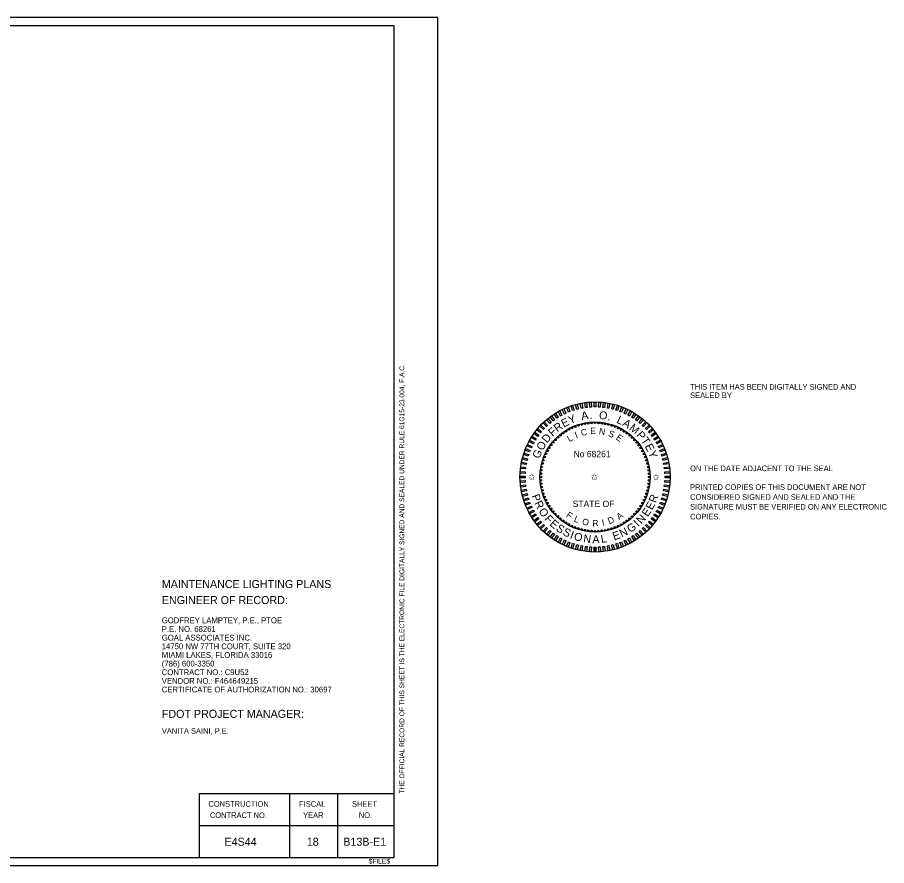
# Model space of a CAD drawing. Extents: x -820.2 to -798.1, y -2199.1 to -2188.5.
# Drawn here: x -808.98 to -798.12, y -2199.12 to -2188.52 of the extents above; entities that cross this region are included whole.
import ezdxf

# ---------------------------------------------------------------- set-up
doc = ezdxf.new("R2010")
doc.units = 0
for name, color, linetype in [('ActivePointCell_dp', 7, 'Continuous'), ('AdhocPoint_dp', 7, 'Continuous'), ('Logo_dp', 7, 'Continuous'), ('NonPlottingEle_dp', 7, 'Continuous'), ('PlotBorder_dp', 7, 'Continuous'), ('SheetBorder_dp', 7, 'Continuous'), ('SheetLines_dp', 7, 'Continuous'), ('TextLabel', 7, 'Continuous'), ('TextMinor', 7, 'Continuous'), ('TextMisc', 7, 'Continuous'), ('TextNotes', 7, 'Continuous')]:
    doc.layers.add(name, color=color, linetype=linetype)

msp = doc.modelspace()

# ---------------------------------------------------------------- linework, layer by layer
at = {"layer": 'ActivePointCell_dp'}
msp.add_line((-804.277, -2188.624), (-804.277, -2188.624), dxfattribs=at)
at = {"layer": 'AdhocPoint_dp'}
msp.add_line((-803.727, -2199.124), (-803.727, -2199.124), dxfattribs=at)
at = {"layer": 'Logo_dp'}
for p, q in [((-801.773, -2195.205), (-801.774, -2195.142)), ((-801.763, -2195.205), (-801.764, -2195.142)), ((-801.753, -2195.204), (-801.754, -2195.142))]:
    msp.add_line(p, q, dxfattribs=at)
for points in [[(-801.917, -2193.406), (-801.937, -2193.409), (-801.949, -2193.348), (-801.929, -2193.344)], [(-801.863, -2193.398), (-801.883, -2193.4), (-801.891, -2193.338), (-801.871, -2193.336)], [(-801.808, -2193.393), (-801.828, -2193.394), (-801.832, -2193.332), (-801.812, -2193.331)], [(-801.753, -2193.392), (-801.773, -2193.392), (-801.773, -2193.33), (-801.753, -2193.33)], [(-801.698, -2193.394), (-801.718, -2193.393), (-801.714, -2193.331), (-801.694, -2193.332)], [(-801.644, -2193.4), (-801.664, -2193.398), (-801.656, -2193.336), (-801.636, -2193.338)], [(-801.589, -2193.409), (-801.609, -2193.406), (-801.598, -2193.344), (-801.578, -2193.348)], [(-802.176, -2193.495), (-802.194, -2193.505), (-802.224, -2193.45), (-802.206, -2193.441)], [(-802.127, -2193.471), (-802.145, -2193.48), (-802.172, -2193.423), (-802.153, -2193.414)], [(-802.076, -2193.45), (-802.095, -2193.457), (-802.118, -2193.399), (-802.099, -2193.392)], [(-802.024, -2193.432), (-802.043, -2193.438), (-802.063, -2193.379), (-802.043, -2193.372)], [(-801.971, -2193.417), (-801.991, -2193.422), (-802.006, -2193.361), (-801.987, -2193.356)], [(-801.536, -2193.422), (-801.555, -2193.417), (-801.54, -2193.357), (-801.52, -2193.362)], [(-801.483, -2193.438), (-801.502, -2193.432), (-801.483, -2193.372), (-801.464, -2193.379)], [(-801.432, -2193.457), (-801.451, -2193.45), (-801.428, -2193.392), (-801.409, -2193.399)], [(-801.382, -2193.48), (-801.4, -2193.471), (-801.373, -2193.415), (-801.355, -2193.423)], [(-801.333, -2193.505), (-801.351, -2193.495), (-801.321, -2193.441), (-801.303, -2193.45)], [(-802.313, -2193.586), (-802.329, -2193.599), (-802.369, -2193.551), (-802.353, -2193.538)], [(-802.269, -2193.553), (-802.286, -2193.565), (-802.323, -2193.514), (-802.306, -2193.503)], [(-802.224, -2193.523), (-802.241, -2193.534), (-802.274, -2193.481), (-802.257, -2193.47)], [(-801.286, -2193.534), (-801.303, -2193.523), (-801.27, -2193.47), (-801.252, -2193.481)], [(-801.241, -2193.565), (-801.257, -2193.553), (-801.22, -2193.503), (-801.204, -2193.515)], [(-801.198, -2193.599), (-801.213, -2193.586), (-801.174, -2193.538), (-801.158, -2193.551)], [(-802.431, -2193.701), (-802.444, -2193.717), (-802.492, -2193.677), (-802.479, -2193.662)], [(-802.394, -2193.661), (-802.408, -2193.675), (-802.454, -2193.633), (-802.44, -2193.618)], [(-802.355, -2193.622), (-802.37, -2193.636), (-802.412, -2193.59), (-802.398, -2193.577)], [(-801.157, -2193.636), (-801.172, -2193.622), (-801.129, -2193.577), (-801.114, -2193.591)], [(-801.119, -2193.675), (-801.132, -2193.661), (-801.087, -2193.618), (-801.073, -2193.633)], [(-801.083, -2193.717), (-801.096, -2193.702), (-801.047, -2193.662), (-801.035, -2193.677)], [(-802.497, -2193.79), (-802.508, -2193.807), (-802.56, -2193.773), (-802.549, -2193.756)], [(-802.465, -2193.744), (-802.477, -2193.761), (-802.528, -2193.724), (-802.516, -2193.708)], [(-801.049, -2193.761), (-801.061, -2193.745), (-801.011, -2193.708), (-800.999, -2193.724)], [(-801.019, -2193.807), (-801.03, -2193.79), (-800.977, -2193.756), (-800.966, -2193.773)], [(-802.551, -2193.885), (-802.559, -2193.903), (-802.616, -2193.877), (-802.607, -2193.859)], [(-802.525, -2193.837), (-802.535, -2193.854), (-802.59, -2193.824), (-802.58, -2193.806)], [(-800.992, -2193.854), (-801.001, -2193.837), (-800.947, -2193.807), (-800.937, -2193.824)], [(-800.967, -2193.904), (-800.976, -2193.885), (-800.919, -2193.859), (-800.911, -2193.877)], [(-802.592, -2193.987), (-802.599, -2194.006), (-802.658, -2193.987), (-802.652, -2193.968)], [(-802.573, -2193.935), (-802.581, -2193.954), (-802.639, -2193.931), (-802.631, -2193.912)], [(-800.946, -2193.954), (-800.953, -2193.936), (-800.895, -2193.913), (-800.888, -2193.931)], [(-800.928, -2194.006), (-800.934, -2193.987), (-800.875, -2193.968), (-800.869, -2193.987)], [(-802.621, -2194.093), (-802.625, -2194.113), (-802.686, -2194.101), (-802.682, -2194.081)], [(-802.608, -2194.04), (-802.613, -2194.059), (-802.674, -2194.044), (-802.669, -2194.024)], [(-800.913, -2194.059), (-800.918, -2194.04), (-800.858, -2194.024), (-800.853, -2194.044)], [(-800.902, -2194.113), (-800.906, -2194.093), (-800.844, -2194.082), (-800.841, -2194.101)], [(-802.636, -2194.202), (-802.637, -2194.222), (-802.7, -2194.218), (-802.698, -2194.198)], [(-802.63, -2194.147), (-802.633, -2194.167), (-802.695, -2194.159), (-802.692, -2194.139)], [(-800.894, -2194.167), (-800.897, -2194.147), (-800.835, -2194.14), (-800.832, -2194.16)], [(-800.889, -2194.222), (-800.891, -2194.202), (-800.828, -2194.198), (-800.827, -2194.218)], [(-802.638, -2194.257), (-802.638, -2194.277), (-802.701, -2194.277), (-802.701, -2194.257)], [(-802.637, -2194.312), (-802.636, -2194.332), (-802.698, -2194.336), (-802.7, -2194.316)], [(-800.891, -2194.332), (-800.889, -2194.312), (-800.827, -2194.316), (-800.828, -2194.336)], [(-800.888, -2194.277), (-800.888, -2194.257), (-800.826, -2194.257), (-800.826, -2194.277)], [(-802.633, -2194.367), (-802.63, -2194.387), (-802.692, -2194.394), (-802.695, -2194.374)], [(-802.625, -2194.421), (-802.621, -2194.441), (-802.682, -2194.453), (-802.686, -2194.433)], [(-800.906, -2194.441), (-800.902, -2194.421), (-800.841, -2194.433), (-800.844, -2194.453)], [(-800.897, -2194.387), (-800.894, -2194.367), (-800.832, -2194.375), (-800.835, -2194.395)], [(-802.613, -2194.475), (-802.608, -2194.494), (-802.669, -2194.51), (-802.674, -2194.49)], [(-802.599, -2194.528), (-802.592, -2194.547), (-802.652, -2194.566), (-802.658, -2194.547)], [(-800.934, -2194.547), (-800.928, -2194.528), (-800.869, -2194.547), (-800.875, -2194.566)], [(-800.918, -2194.494), (-800.913, -2194.475), (-800.853, -2194.49), (-800.858, -2194.51)], [(-802.581, -2194.58), (-802.573, -2194.598), (-802.631, -2194.621), (-802.639, -2194.603)], [(-802.559, -2194.63), (-802.551, -2194.649), (-802.607, -2194.675), (-802.616, -2194.657)], [(-800.976, -2194.649), (-800.967, -2194.631), (-800.911, -2194.657), (-800.919, -2194.675)], [(-800.954, -2194.599), (-800.946, -2194.58), (-800.888, -2194.603), (-800.895, -2194.622)], [(-802.535, -2194.68), (-802.525, -2194.697), (-802.58, -2194.727), (-802.59, -2194.71)], [(-802.508, -2194.727), (-802.497, -2194.744), (-802.55, -2194.778), (-802.56, -2194.761)], [(-801.03, -2194.744), (-801.019, -2194.727), (-800.966, -2194.761), (-800.977, -2194.778)], [(-801.001, -2194.697), (-800.992, -2194.68), (-800.937, -2194.71), (-800.947, -2194.728)], [(-802.477, -2194.773), (-802.465, -2194.789), (-802.516, -2194.826), (-802.528, -2194.81)], [(-802.444, -2194.817), (-802.431, -2194.832), (-802.479, -2194.872), (-802.492, -2194.857)], [(-802.408, -2194.859), (-802.394, -2194.873), (-802.44, -2194.916), (-802.454, -2194.901)], [(-801.132, -2194.873), (-801.119, -2194.859), (-801.073, -2194.901), (-801.087, -2194.916)], [(-801.096, -2194.833), (-801.083, -2194.817), (-801.035, -2194.857), (-801.048, -2194.872)], [(-801.061, -2194.79), (-801.05, -2194.773), (-800.999, -2194.81), (-801.011, -2194.826)], [(-802.37, -2194.898), (-802.355, -2194.912), (-802.398, -2194.957), (-802.413, -2194.943)], [(-802.329, -2194.935), (-802.313, -2194.948), (-802.353, -2194.996), (-802.369, -2194.983)], [(-802.286, -2194.969), (-802.27, -2194.981), (-802.306, -2195.031), (-802.323, -2195.019)], [(-801.257, -2194.981), (-801.241, -2194.969), (-801.204, -2195.02), (-801.221, -2195.031)], [(-801.213, -2194.948), (-801.198, -2194.935), (-801.158, -2194.983), (-801.174, -2194.996)], [(-801.172, -2194.912), (-801.157, -2194.898), (-801.114, -2194.944), (-801.129, -2194.957)], [(-802.241, -2195), (-802.224, -2195.011), (-802.257, -2195.064), (-802.274, -2195.053)], [(-802.194, -2195.029), (-802.176, -2195.039), (-802.206, -2195.093), (-802.224, -2195.084)], [(-802.145, -2195.054), (-802.127, -2195.063), (-802.153, -2195.12), (-802.172, -2195.111)], [(-802.095, -2195.077), (-802.076, -2195.084), (-802.099, -2195.142), (-802.118, -2195.135)], [(-801.451, -2195.084), (-801.432, -2195.077), (-801.409, -2195.135), (-801.428, -2195.142)], [(-801.4, -2195.063), (-801.382, -2195.055), (-801.355, -2195.111), (-801.373, -2195.12)], [(-801.351, -2195.039), (-801.333, -2195.029), (-801.303, -2195.084), (-801.321, -2195.093)], [(-801.303, -2195.011), (-801.286, -2195), (-801.253, -2195.053), (-801.27, -2195.064)], [(-802.043, -2195.096), (-802.024, -2195.102), (-802.044, -2195.162), (-802.063, -2195.155)], [(-801.991, -2195.112), (-801.971, -2195.117), (-801.987, -2195.178), (-802.006, -2195.172)], [(-801.937, -2195.125), (-801.918, -2195.128), (-801.929, -2195.19), (-801.949, -2195.186)], [(-801.883, -2195.134), (-801.863, -2195.136), (-801.871, -2195.198), (-801.891, -2195.196)], [(-801.828, -2195.14), (-801.808, -2195.141), (-801.812, -2195.203), (-801.832, -2195.202)], [(-801.774, -2195.142), (-801.753, -2195.142), (-801.753, -2195.204), (-801.774, -2195.204)], [(-801.719, -2195.141), (-801.698, -2195.14), (-801.695, -2195.202), (-801.715, -2195.203)], [(-801.664, -2195.136), (-801.644, -2195.134), (-801.636, -2195.196), (-801.656, -2195.198)], [(-801.609, -2195.128), (-801.59, -2195.125), (-801.578, -2195.186), (-801.598, -2195.19)], [(-801.556, -2195.117), (-801.536, -2195.112), (-801.521, -2195.173), (-801.54, -2195.178)], [(-801.503, -2195.102), (-801.483, -2195.096), (-801.464, -2195.156), (-801.483, -2195.162)]]:
    msp.add_lwpolyline(points, close=True, dxfattribs=at)
for centre in [(-802.089, -2193.673), (-802.051, -2193.654), (-802.012, -2193.637), (-801.972, -2193.623), (-801.931, -2193.611), (-801.89, -2193.601), (-801.848, -2193.595), (-801.805, -2193.591), (-801.763, -2193.59), (-801.72, -2193.591), (-801.678, -2193.595), (-801.636, -2193.602), (-801.594, -2193.611), (-801.553, -2193.623), (-801.513, -2193.637), (-801.474, -2193.654), (-801.437, -2193.674), (-802.227, -2193.773), (-802.195, -2193.745), (-802.161, -2193.719), (-802.126, -2193.695), (-801.4, -2193.695), (-801.365, -2193.719), (-801.331, -2193.745), (-801.299, -2193.774), (-802.311, -2193.868), (-802.285, -2193.835), (-802.257, -2193.803), (-801.269, -2193.804), (-801.241, -2193.836), (-801.215, -2193.869), (-802.376, -2193.978), (-802.357, -2193.94), (-802.335, -2193.904), (-801.191, -2193.904), (-801.169, -2193.941), (-801.15, -2193.979), (-802.419, -2194.098), (-802.408, -2194.057), (-802.393, -2194.017), (-801.133, -2194.018), (-801.119, -2194.058), (-801.107, -2194.099), (-802.439, -2194.224), (-802.435, -2194.182), (-802.429, -2194.14), (-801.098, -2194.141), (-801.091, -2194.183), (-801.087, -2194.225), (-802.441, -2194.266), (-802.44, -2194.309), (-801.087, -2194.31), (-801.086, -2194.268), (-802.436, -2194.351), (-802.429, -2194.393), (-802.42, -2194.435), (-801.107, -2194.436), (-801.098, -2194.395), (-801.091, -2194.352), (-802.408, -2194.476), (-802.393, -2194.516), (-801.134, -2194.517), (-801.119, -2194.477), (-802.377, -2194.555), (-802.357, -2194.593), (-802.336, -2194.63), (-801.192, -2194.63), (-801.17, -2194.594), (-801.151, -2194.556), (-802.312, -2194.665), (-802.286, -2194.698), (-802.258, -2194.73), (-802.228, -2194.76), (-801.3, -2194.761), (-801.27, -2194.731), (-801.242, -2194.699), (-801.216, -2194.666), (-802.196, -2194.789), (-802.162, -2194.815), (-802.127, -2194.839), (-802.09, -2194.86), (-802.052, -2194.88), (-801.475, -2194.88), (-801.438, -2194.861), (-801.401, -2194.839), (-801.366, -2194.815), (-801.332, -2194.789), (-802.013, -2194.897), (-801.973, -2194.911), (-801.932, -2194.923), (-801.891, -2194.932), (-801.849, -2194.939), (-801.806, -2194.943), (-801.763, -2194.945), (-801.721, -2194.943), (-801.679, -2194.939), (-801.637, -2194.933), (-801.595, -2194.923), (-801.555, -2194.911), (-801.515, -2194.897)]:
    msp.add_circle(centre, 0.01, dxfattribs=at)
at = {"layer": 'NonPlottingEle_dp'}
for radius in [0.938, 0.688]:
    msp.add_circle((-801.763, -2194.267), radius, dxfattribs=at)
at = {"layer": 'PlotBorder_dp'}
msp.add_lwpolyline([(-820.227, -2199.124), (-803.727, -2199.124), (-803.727, -2188.524), (-820.227, -2188.524)], close=True, dxfattribs=at)
at = {"layer": 'SheetBorder_dp'}
for p, q in [((-819.677, -2188.624), (-804.277, -2188.624)), ((-804.277, -2188.624), (-804.277, -2199.024)), ((-819.677, -2199.024), (-804.277, -2199.024))]:
    msp.add_line(p, q, dxfattribs=at)
at = {"layer": 'SheetLines_dp'}
for p, q in [((-806.708, -2198.224), (-804.277, -2198.224)), ((-806.708, -2199.024), (-806.708, -2198.224)), ((-805.577, -2199.024), (-805.577, -2198.224)), ((-804.977, -2199.024), (-804.977, -2198.224)), ((-806.708, -2198.624), (-804.277, -2198.624))]:
    msp.add_line(p, q, dxfattribs=at)

# ---------------------------------------------------------------- texts
at = {"layer": 'Logo_dp'}
for s, height, rotation, p in [('A', 0.1, 8.8088, (-801.928, -2193.556)), ('O', 0.1, 352.1877, (-801.718, -2193.539)), ('E', 0.1, 28.1055, (-802.154, -2193.651)), ('Y', 0.1, 21.0633, (-802.075, -2193.608)), ('.', 0.1, 1.0418, (-801.831, -2193.541)), ('.', 0.1, 343.5268, (-801.609, -2193.554)), ('L', 0.1, 334.6727, (-801.501, -2193.586)), ('A', 0.1, 328.4096, (-801.428, -2193.619)), ('F', 0.1, 42.3772, (-802.294, -2193.766)), ('R', 0.1, 35.9269, (-802.234, -2193.71)), ('C', 0.08, 12.2025, (-801.931, -2193.755)), ('E', 0.08, 0.4186, (-801.823, -2193.732)), ('N', 0.08, 349.2914, (-801.719, -2193.73)), ('M', 0.1, 320.6426, (-801.344, -2193.67)), ('D', 0.1, 50.8569, (-802.362, -2193.85)), ('L', 0.08, 30.4021, (-802.083, -2193.833)), ('I', 0.08, 20.0117, (-801.999, -2193.783)), ('S', 0.08, 337.0221, (-801.606, -2193.752)), ('E', 0.08, 325.8663, (-801.509, -2193.792)), ('P', 0.1, 311.1966, (-801.252, -2193.747)), ('T', 0.1, 304.4563, (-801.194, -2193.811)), ('O', 0.1, 59.5178, (-802.418, -2193.945)), ('E', 0.1, 297.6315, (-801.144, -2193.882)), ('G', 0.1, 68.0518, (-802.458, -2194.045)), ('Y', 0.1, 290.5893, (-801.101, -2193.96)), ('P', 0.1, 289.4055, (-802.558, -2194.502)), ('R', 0.1, 69.5134, (-801.003, -2194.597)), ('R', 0.1, 296.1458, (-802.525, -2194.593)), ('E', 0.1, 55.4289, (-801.106, -2194.772)), ('E', 0.1, 62.4712, (-801.049, -2194.687)), ('O', 0.1, 303.9671, (-802.474, -2194.694)), ('F', 0.1, 312.628, (-802.401, -2194.796)), ('F', 0.08, 328.7241, (-802.131, -2194.764)), ('L', 0.08, 339.2916, (-802.034, -2194.823)), ('A', 0.08, 34.4992, (-801.462, -2194.806)), ('N', 0.1, 47.1788, (-801.186, -2194.861)), ('E', 0.1, 319.0783, (-802.338, -2194.864)), ('S', 0.1, 326.1206, (-802.26, -2194.93)), ('O', 0.08, 349.6821, (-801.929, -2194.862)), ('R', 0.08, 2.3398, (-801.795, -2194.884)), ('I', 0.08, 14.2037, (-801.667, -2194.878)), ('D', 0.08, 22.0128, (-801.585, -2194.859)), ('G', 0.1, 35.1115, (-801.322, -2194.969)), ('I', 0.1, 43.6456, (-801.223, -2194.895)), ('S', 0.1, 333.193, (-802.175, -2194.986)), ('I', 0.1, 340.2654, (-802.083, -2195.031)), ('O', 0.1, 343.7986, (-802.035, -2195.05)), ('E', 0.1, 19.8191, (-801.523, -2195.06)), ('N', 0.1, 26.8614, (-801.428, -2195.025)), ('N', 0.1, 352.4595, (-801.914, -2195.082)), ('A', 0.1, 0.7097, (-801.796, -2195.095)), ('L', 0.1, 8.4767, (-801.684, -2195.092))]:
    msp.add_text(s, height=height, rotation=rotation, dxfattribs=at).set_placement(p)
for s, p in [('No 68261', (-802.032, -2194.02)), ('✩', (-802.598, -2194.305)), ('✩', (-801.814, -2194.305)), ('✩', (-801.042, -2194.305)), ('STATE OF', (-802.043, -2194.643))]:
    msp.add_text(s, height=0.08, dxfattribs=at).set_placement(p)
at = {"layer": 'TextLabel'}
for s, height, p in [('MAINTENANCE LIGHTING PLANS', 0.1, (-807.177, -2195.655)), ('ENGINEER OF RECORD:', 0.1, (-807.177, -2195.855)), ('GODFREY LAMPTEY, P.E., PTOE', 0.07202, (-807.178, -2196.094)), ('P.E. NO. 68261', 0.07202, (-807.178, -2196.203)), ('GOAL ASSOCIATES INC. ', 0.07202, (-807.178, -2196.311)), ('14750 NW 77TH COURT, SUITE 320', 0.07202, (-807.178, -2196.419)), ('MIAMI LAKES, FLORIDA 33016', 0.07202, (-807.178, -2196.527)), ('(786) 600-3350', 0.07202, (-807.178, -2196.635)), ('CONTRACT NO.: C9U52', 0.07202, (-807.178, -2196.743)), ('VENDOR NO.: F464649215', 0.07202, (-807.178, -2196.851)), ('CERTIFICATE OF AUTHORIZATION NO.: 30697', 0.07202, (-807.178, -2196.959)), ('E4S44', 0.1, (-806.394, -2198.875)), ('18', 0.1, (-805.365, -2198.875)), ('B13B-E1', 0.1, (-804.909, -2198.875))]:
    msp.add_text(s, height=height, dxfattribs=at).set_placement(p)
at = {"layer": 'TextMinor'}
msp.add_text('$FILE$', height=0.06, dxfattribs=at).set_placement((-804.592, -2199.099))
at = {"layer": 'TextMisc'}
msp.add_text('THE OFFICIAL RECORD OF THIS SHEET IS THE ELECTRONIC FILE DIGITALLY SIGNED AND SEALED UNDER RULE 61G15-23.004, F.A.C.', height=0.06, rotation=90, dxfattribs=at).set_placement((-804.147, -2198.224))
for s, p in [('THIS ITEM HAS BEEN DIGITALLY SIGNED AND ', (-800.574, -2193.176)), ('SEALED BY', (-800.574, -2193.281)), ('ON THE DATE ADJACENT TO THE SEAL', (-800.575, -2194.194)), ('PRINTED COPIES OF THIS DOCUMENT ARE NOT ', (-800.575, -2194.429)), ('CONSIDERED SIGNED AND SEALED AND THE ', (-800.575, -2194.552)), ('SIGNATURE MUST BE VERIFIED ON ANY ELECTRONIC ', (-800.575, -2194.674)), ('COPIES.', (-800.575, -2194.797))]:
    msp.add_text(s, height=0.07, dxfattribs=at).set_placement(p)
at = {"layer": 'TextNotes'}
for s, height, p in [('FDOT PROJECT MANAGER:', 0.1, (-807.177, -2197.277)), ('VANITA SAINI, P.E.', 0.07, (-807.177, -2197.476))]:
    msp.add_text(s, height=height, dxfattribs=at).set_placement(p)
for s, p in [('CONSTRUCTION', (-806.595, -2198.387)), ('FISCAL', (-805.461, -2198.388)), ('SHEET', (-804.801, -2198.388)), ('CONTRACT NO.', (-806.576, -2198.528)), ('YEAR', (-805.411, -2198.528)), ('NO.', (-804.715, -2198.528))]:
    msp.add_text(s, height=0.07, rotation=359.8607, dxfattribs=at).set_placement(p)

doc.saveas('drawing.dxf')
